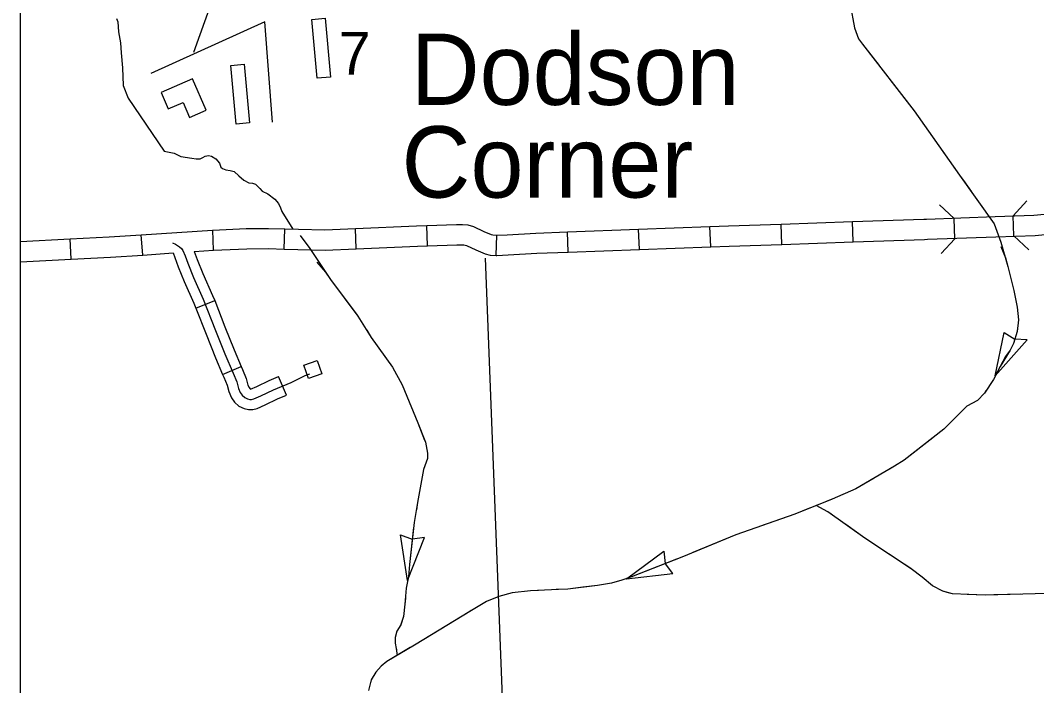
# Model space of a CAD drawing. Extents: x 155 to 3386, y 68 to 2138.
# Drawn here: x 1150.5 to 1365.4, y 937.9 to 1078.7 of the extents above; entities that cross this region are included whole.
import ezdxf

# ---------------------------------------------------------------- set-up
doc = ezdxf.new("R2010")
doc.units = 0
for name, color, linetype in [('Default', 7, 'Continuous'), ('E_No Plot', 7, 'Continuous'), ('Level 24', 7, 'Continuous'), ('Level 32', 7, 'Continuous'), ('Level 35', 7, 'Continuous'), ('Level 38', 7, 'Continuous'), ('Level 4', 7, 'Continuous'), ('Level 43', 7, 'Continuous'), ('Level 56', 7, 'Continuous'), ('Level 58', 7, 'Continuous')]:
    doc.layers.add(name, color=color, linetype=linetype)

msp = doc.modelspace()

# ---------------------------------------------------------------- linework, layer by layer
at = {"layer": 'Default'}
msp.add_lwpolyline([(1150.5, 1308.99), (2342.15, 1308.99), (2342.15, 348.58), (1150.5, 348.58)], close=True, dxfattribs=at)
at = {"layer": 'E_No Plot'}
msp.add_lwpolyline([(1150.5, 1308.99), (2342.15, 1308.99), (2342.15, 348.58), (1150.5, 348.58)], close=True, dxfattribs=at)
msp.add_lwpolyline([(1150.5, 1308.99), (2342.15, 1308.99), (2342.15, 348.58), (1150.5, 348.58)], close=True, dxfattribs=at)
at = {"layer": 'Level 32'}
for p, q in [((1326.6, 1031.83), (1326.45, 1036.11)), ((1348.11, 1032.49), (1347.95, 1036.77)), ((1360.56, 1033.08), (1360.4, 1037.37)), ((1191.37, 1030.05), (1191.18, 1034.33)), ((1206.29, 1030.29), (1206.42, 1034.58)), ((1221.52, 1030.38), (1221.33, 1034.66)), ((1236.57, 1031.02), (1236.43, 1035.31)), ((1266.3, 1029.66), (1266.15, 1033.94)), ((1281.38, 1030.21), (1281.22, 1034.5)), ((1296.46, 1030.77), (1296.3, 1035.05)), ((1311.53, 1031.3), (1311.38, 1035.58)), ((1161.27, 1028.16), (1161.05, 1032.44)), ((1176.37, 1029.04), (1176.08, 1033.32)), ((1251.08, 1028.98), (1251.23, 1033.27)), ((1187.6, 1017.83), (1191.59, 1019.4)), ((1193.27, 1003.79), (1197.21, 1005.46)), ((1206.74, 999.37), (1205.09, 1003.33))]:
    msp.add_line(p, q, dxfattribs=at)
for points in [[(1356.6, 1037.18), (1364.8, 1037.48), (1371.53, 1038.13)], [(1311.38, 1035.58), (1326.45, 1036.11)], [(1326.45, 1036.11), (1341.53, 1036.64)], [(1341.53, 1036.64), (1342.12, 1036.66), (1356.6, 1037.18)], [(1176.08, 1033.32), (1191.11, 1034.33), (1191.18, 1034.33)], [(1191.18, 1034.33), (1198.27, 1034.64), (1203, 1034.69), (1206.42, 1034.58)], [(1206.42, 1034.58), (1209.3, 1034.49), (1214.9, 1034.37), (1221.33, 1034.66)], [(1221.33, 1034.66), (1234.28, 1035.24), (1236.43, 1035.31)], [(1236.43, 1035.31), (1242.73, 1035.51), (1244.01, 1035.51), (1245.08, 1035.41), (1246.3, 1035.07), (1248.52, 1034.03), (1250.08, 1033.37), (1250.41, 1033.3), (1251.23, 1033.27)], [(1251.23, 1033.27), (1251.24, 1033.27), (1253.46, 1033.34), (1259.49, 1033.7), (1266.15, 1033.94)], [(1266.15, 1033.94), (1281.22, 1034.5)], [(1281.22, 1034.5), (1296.3, 1035.05)], [(1296.3, 1035.05), (1300.25, 1035.2), (1311.38, 1035.58)], [(1356.76, 1032.9), (1365.08, 1033.2), (1371.94, 1033.86)], [(1150.5, 1031.9), (1161.05, 1032.44)], [(1161.05, 1032.44), (1169.3, 1032.87), (1176.08, 1033.32)], [(1182.68, 1031.61), (1183.27, 1031.34), (1183.72, 1031.08), (1184.14, 1030.79), (1184.56, 1030.4), (1184.86, 1029.98), (1185.34, 1028.84), (1185.9, 1027.32), (1187.13, 1024.3), (1189.17, 1019.68), (1191.77, 1013.09), (1193.74, 1008.15), (1195.49, 1004.03), (1196.24, 1002.21), (1196.6, 1000.84), (1196.99, 999.93), (1197.41, 999.38), (1197.93, 998.9), (1198.54, 998.6), (1199, 998.51), (1199.39, 998.51), (1199.84, 998.64), (1201.37, 999.29), (1204, 1000.55), (1207.73, 1002.11), (1210.75, 1003.54), (1211.74, 1003.9)], [(1311.53, 1031.3), (1326.6, 1031.83)], [(1326.6, 1031.83), (1341.68, 1032.35)], [(1341.68, 1032.35), (1342.27, 1032.37), (1356.76, 1032.9)], [(1176.37, 1029.04), (1182.84, 1029.48)], [(1182.84, 1029.48), (1183.89, 1026.55), (1185.16, 1023.46), (1187.2, 1018.86), (1187.6, 1017.83)], [(1187.28, 1029.78), (1191.35, 1030.05), (1191.37, 1030.05)], [(1187.28, 1029.78), (1187.9, 1028.09), (1189.1, 1025.14), (1191.15, 1020.51), (1191.59, 1019.4)], [(1191.37, 1030.05), (1198.38, 1030.36), (1202.95, 1030.4), (1206.29, 1030.29)], [(1206.29, 1030.29), (1209.19, 1030.2), (1214.95, 1030.08), (1221.52, 1030.38)], [(1221.52, 1030.38), (1234.45, 1030.95), (1236.57, 1031.02)], [(1236.57, 1031.02), (1242.8, 1031.23), (1243.8, 1031.23), (1244.3, 1031.18), (1244.81, 1031.04), (1246.77, 1030.11), (1248.77, 1029.27), (1249.86, 1029.03), (1251.08, 1028.98)], [(1251.08, 1028.98), (1251.24, 1028.98), (1253.66, 1029.06), (1259.7, 1029.42), (1266.3, 1029.66)], [(1266.3, 1029.66), (1281.38, 1030.21)], [(1281.38, 1030.21), (1296.46, 1030.77)], [(1296.46, 1030.77), (1300.4, 1030.91), (1311.53, 1031.3)], [(1150.5, 1027.61), (1161.27, 1028.16)], [(1161.27, 1028.16), (1169.55, 1028.59), (1176.37, 1029.04)], [(1191.59, 1019.4), (1193.76, 1013.88), (1195.72, 1008.97), (1197.21, 1005.46)], [(1187.6, 1017.83), (1189.78, 1012.3), (1191.76, 1007.33), (1193.27, 1003.79)], [(1193.27, 1003.79), (1193.52, 1003.2), (1194.2, 1001.53), (1194.56, 1000.15), (1195.12, 998.85), (1195.81, 997.94), (1196.71, 997.1), (1197.85, 996.56), (1198.77, 996.36), (1199.69, 996.36), (1200.56, 996.61), (1202.25, 997.33), (1204.87, 998.6), (1206.74, 999.37)], [(1197.21, 1005.46), (1197.47, 1004.85), (1198.28, 1002.89), (1198.63, 1001.54), (1198.85, 1001.02), (1199, 1000.82), (1199.15, 1000.69), (1199.17, 1000.68), (1200.48, 1001.24), (1203.12, 1002.51), (1205.09, 1003.33)]]:
    msp.add_lwpolyline(points, dxfattribs=at)
at = {"layer": 'Level 35'}
for points in [[(1325.95, 1082.01), (1326.89, 1077.13), (1327.72, 1074.75), (1328.59, 1073.62)], [(1170.81, 1079.11), (1171.11, 1078.37), (1171.28, 1076.26), (1171.7, 1073.91), (1171.83, 1071.83), (1172.11, 1068.64), (1172.25, 1064.9), (1173.32, 1062.2), (1180.94, 1051.01), (1183.04, 1050.56), (1184.43, 1049.87), (1186.76, 1049.56), (1187.67, 1049.39), (1188.53, 1049.43), (1189.05, 1049.65), (1189.57, 1049.95), (1190.27, 1050.13), (1190.92, 1049.95), (1191.83, 1049.43), (1192.62, 1048.47), (1192.92, 1047.65), (1193.23, 1047.34), (1193.96, 1047.08), (1194.87, 1046.95), (1195.7, 1046.69), (1196.7, 1045.78), (1197.78, 1044.91), (1198.82, 1044.31), (1199.56, 1044.26), (1200.25, 1044.05), (1201.12, 1043.09), (1201.64, 1042.53), (1202.85, 1041.96), (1204.28, 1040.84), (1205.06, 1039.97), (1205.49, 1039.06), (1205.8, 1038.24), (1208.12, 1034.52)]]:
    msp.add_lwpolyline(points, dxfattribs=at)
at = {"layer": 'Level 38'}
for points in [[(1360.4, 1037.37), (1363.32, 1040.5)], [(1344.82, 1039.69), (1347.95, 1036.77)], [(1348.11, 1032.49), (1345.19, 1029.35)], [(1363.7, 1030.16), (1360.56, 1033.08)]]:
    msp.add_lwpolyline(points, dxfattribs=at)
at = {"layer": 'Level 4'}
msp.add_lwpolyline([(1248.81, 1028.41), (1253.05, 917.17)], dxfattribs=at)
at = {"layer": 'Level 43'}
for p, q in [((1356.64, 1003.5), (1358.53, 1012.63)), ((1358.53, 1012.63), (1360.73, 1011.23)), ((1356.64, 1003.5), (1363.37, 1011.11)), ((1363.37, 1011.11), (1360.77, 1011.22)), ((1232.37, 960.18), (1230.91, 969.88)), ((1230.91, 969.88), (1233.34, 968.92)), ((1232.37, 960.18), (1235.96, 969.31)), ((1235.96, 969.31), (1233.38, 968.92)), ((1278.69, 960.54), (1286.56, 966.38)), ((1286.56, 966.38), (1286.86, 963.78)), ((1288.43, 961.66), (1286.88, 963.75)), ((1278.69, 960.54), (1288.43, 961.66))]:
    msp.add_line(p, q, dxfattribs=at)
for points in [[(1328.59, 1073.62), (1339.49, 1059.54), (1349.1, 1045.91), (1356.42, 1035.62), (1357.8, 1031.78), (1359.31, 1026.65), (1360.54, 1021.52), (1361.29, 1018.04), (1361.51, 1015.36), (1361.25, 1012.84), (1360.46, 1010.31), (1359.81, 1008.94), (1358.76, 1007.56), (1357.68, 1005.47), (1356.24, 1002.72), (1354.36, 999.83), (1352.84, 998.25), (1350.64, 997.05), (1345.73, 992.21), (1337.36, 985.64), (1335.34, 984.38), (1327.18, 979.57), (1322.12, 977.37), (1314.22, 974.23), (1301.8, 969.82), (1290.39, 965.16), (1279.75, 960.95), (1277.65, 960.23), (1275.49, 959.65), (1272.53, 959.11), (1266.24, 958.39), (1264.26, 958.28), (1258.34, 957.99), (1254.48, 957.59), (1251.7, 956.8), (1249.06, 955.75), (1245.56, 953.66), (1233.83, 946.54), (1228.02, 943.03), (1226.79, 942.09), (1225.67, 940.79), (1224.7, 939.17), (1224.08, 936.93)], [(1328.59, 1073.62), (1332.05, 1069.15)], [(1334.36, 1066.17), (1339.49, 1059.54), (1341.18, 1057.14)], [(1343.35, 1054.06), (1349.1, 1045.91), (1349.88, 1044.82), (1351.62, 1042.41)], [(1209.66, 1033.16), (1211.74, 1030.43), (1216.07, 1023.84), (1221.88, 1016.1), (1224.7, 1011.59), (1229.2, 1005.3), (1231.2, 1001.57), (1234.54, 993.55), (1236.14, 989.43), (1236.57, 987.13), (1236.57, 986), (1235.71, 983.7), (1234.49, 976.68), (1233.75, 972.43), (1232.76, 963.58), (1232.58, 961.07), (1232.06, 958.55), (1231.8, 955.17), (1231.54, 952.61), (1230.94, 950.83), (1230.07, 949.44), (1229.72, 948.14), (1229.72, 946.93), (1229.98, 945.8), (1230.19, 944.34)], [(1357.82, 1030.84), (1358.78, 1028.43), (1359.31, 1026.65), (1360.54, 1021.52), (1361.29, 1018.04), (1361.34, 1017.42)], [(1213.2, 1027.53), (1215.03, 1025.42), (1216.07, 1023.84), (1221.73, 1016.3)], [(1223.74, 1013.12), (1224.7, 1011.59), (1229.2, 1005.3), (1230.04, 1003.74)], [(1361.34, 1013.67), (1361.25, 1012.84), (1360.46, 1010.31), (1359.81, 1008.94), (1357.68, 1005.47), (1356.64, 1003.5)], [(1231.7, 1000.36), (1234.54, 993.55), (1235.97, 989.88)], [(1354.66, 1000.29), (1354.36, 999.83), (1352.84, 998.25), (1350.64, 997.05), (1350.35, 996.77)], [(1350.35, 996.77), (1346.32, 992.79)], [(1343.42, 990.4), (1337.36, 985.64), (1335.34, 984.38), (1334.28, 983.75)], [(1236.57, 986.18), (1236.57, 986), (1235.71, 983.7), (1234.49, 976.68), (1234.23, 975.15)], [(1331.03, 981.84), (1327.18, 979.57), (1322.12, 977.37), (1320.88, 976.88)], [(1410.05, 958.56), (1354.51, 957.1), (1347.59, 957.34), (1345.53, 957.95), (1343.34, 959.05), (1341.16, 960.87), (1338.85, 962.69), (1329.02, 969.13), (1321.25, 974.71), (1318.75, 976.03)], [(1321.95, 974.21), (1321.25, 974.71), (1318.75, 976.03)], [(1317.38, 975.49), (1314.22, 974.23), (1306.76, 971.58)], [(1233.64, 971.42), (1232.76, 963.58), (1232.58, 961.07), (1232.4, 960.18)], [(1334.36, 965.63), (1329.02, 969.13), (1325.01, 972.01)], [(1303.21, 970.32), (1301.8, 969.82), (1292.71, 966.11)], [(1289.21, 964.7), (1279.75, 960.95), (1278.67, 960.58)], [(1346.95, 957.53), (1345.53, 957.95), (1343.34, 959.05), (1341.16, 960.87), (1338.85, 962.69), (1337.51, 963.57)], [(1269.45, 958.76), (1266.24, 958.39), (1264.26, 958.28), (1263.82, 958.26)], [(1275.04, 959.57), (1272.53, 959.11), (1269.45, 958.76)], [(1231.9, 956.45), (1231.8, 955.17), (1231.54, 952.61), (1230.96, 950.91)], [(1260.05, 958.07), (1258.34, 957.99), (1254.48, 957.59), (1251.7, 956.8), (1249.07, 955.75)], [(1356.35, 957.15), (1354.51, 957.1), (1350.7, 957.24)], [(1362, 957.3), (1356.35, 957.15)], [(1245.83, 953.82), (1245.56, 953.66), (1236.16, 947.95)], [(1230.96, 950.91), (1230.94, 950.83), (1230.07, 949.44), (1229.72, 948.14), (1229.72, 946.93), (1229.98, 945.8), (1230.01, 945.58)], [(1232.93, 946), (1228.02, 943.03), (1226.79, 942.09), (1225.67, 940.79), (1224.7, 939.17), (1224.58, 938.76)]]:
    msp.add_lwpolyline(points, dxfattribs=at)
at = {"layer": 'Level 56'}
for points in [[(1187.21, 1071.97), (1193.17, 1088.74)], [(1203.79, 1057.12), (1202.17, 1078.38), (1178.07, 1067.43)]]:
    msp.add_lwpolyline(points, dxfattribs=at)
for points in [[(1212.1, 1078.88), (1214.95, 1079.14), (1216.11, 1066.7), (1213.26, 1066.43)], [(1194.97, 1069.16), (1197.81, 1069.43), (1198.97, 1056.98), (1196.13, 1056.72)], [(1210.43, 1005.76), (1213.24, 1006.73), (1214.22, 1003.91), (1211.41, 1002.94)]]:
    msp.add_lwpolyline(points, close=True, dxfattribs=at)
at = {"layer": 'Level 58'}
msp.add_lwpolyline([(1186.91, 1066.34), (1180.25, 1063.45), (1181.77, 1059.94), (1184.92, 1061.3), (1186.28, 1058.16), (1189.79, 1059.68)], close=True, dxfattribs=at)

# ---------------------------------------------------------------- texts
at = {"layer": 'Level 24'}
for s, p in [('Dodson', (1233.03, 1060.81)), ('Corner', (1231.1, 1041.2))]:
    msp.add_text(s, height=15.086, dxfattribs=at).set_placement(p)
at = {"layer": 'Level 56'}
msp.add_text('7', height=9.05, dxfattribs=at).set_placement((1217.79, 1067.21))

doc.saveas('drawing.dxf')
